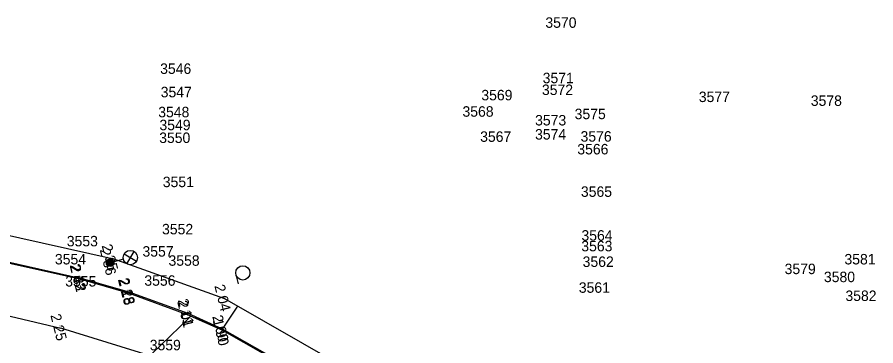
# Model space of a CAD drawing. Extents: x -740053 to -737517, y -1033516 to -1032488.
# Drawn here: x -739094.08 to -739048.92, y -1032573.66 to -1032556.4 of the extents above; entities that cross this region are included whole.
import ezdxf

# ---------------------------------------------------------------- set-up
doc = ezdxf.new("R2010")
doc.units = 0
for name, color, linetype in [('bod-cislo', 7, 'Continuous'), ('bod-oznac', 7, 'Continuous'), ('bod-vyska', 7, 'Continuous'), ('bod-vyska100', 7, 'Continuous'), ('chodnik', 7, 'Continuous'), ('Contours', 7, 'Continuous'), ('el-zariz', 7, 'Continuous'), ('osa-komunikace', 7, 'Continuous'), ('podezdivka', 7, 'Continuous'), ('silnice', 7, 'Continuous'), ('Znacky-kultury', 7, 'Continuous')]:
    doc.layers.add(name, color=color, linetype=linetype)

# ---------------------------------------------------------------- blocks, each defined once
blk = doc.blocks.new('el_lamst')
for p, q in [((-0.53, 1.658), (0.53, 2.719)), ((-0.53, 2.719), (0.53, 1.658)), ((0, 1.439), (0, 0.4))]:
    blk.add_line(p, q)
for centre, radius in [((0, 2.189), 0.75), ((0, 0), 0.4), ((0, 0), 0.351), ((0, 0), 0.305), ((0, 0), 0.305), ((0, 0), 0.26), ((0, 0), 0.206), ((0, 0), 0.161), ((0, 0), 0.115), ((0, 0), 0.0619)]:
    blk.add_circle(centre, radius)
blk = doc.blocks.new('p_zahr')
blk.add_line((0, -0.75), (0.993, -0.75))
blk.add_circle((0, 0), 0.75)
blk = doc.blocks.new('POINT_DISPLAY')
blk.add_line((0, 0), (0, 0))

msp = doc.modelspace()

# ---------------------------------------------------------------- linework, layer by layer
at = {"layer": 'chodnik'}
for p, q in [((-739098.884, -1032568.296), (-739090.768, -1032570.099)), ((-739088.189, -1032570.842), (-739090.768, -1032570.099)), ((-739085.08, -1032571.967), (-739088.189, -1032570.842)), ((-739083.274, -1032572.791), (-739085.08, -1032571.967)), ((-739073.709, -1032578.179), (-739083.274, -1032572.791))]:
    msp.add_line(p, q, dxfattribs=at)
at = {"layer": 'Contours'}
msp.add_lwpolyline([(-739113.301, -1032585.141), (-739112.468, -1032582.989), (-739111.701, -1032582.242), (-739110.056, -1032580.212), (-739109.326, -1032576.302), (-739107.888, -1032575.694), (-739099.85, -1032575.084), (-739095.564, -1032576.081), (-739094.668, -1032576.103), (-739092.396, -1032575.717), (-739091.714, -1032575.641), (-739090.99, -1032575.637), (-739087.57, -1032574.358), (-739087.088, -1032574.182), (-739086.97, -1032574.064), (-739086.008, -1032573.134), (-739085.07, -1032572.23), (-739084.95, -1032572.102), (-739084.144, -1032572.423), (-739083.274, -1032572.791), (-739082.501, -1032571.634), (-739082.49, -1032571.595), (-739082.473, -1032571.58)], dxfattribs=at)
at = {"layer": 'osa-komunikace'}
for p in [(-739099.525, -1032570.912), (-739086.9, -1032574.24)]:
    msp.add_line(p, (-739091.787, -1032572.728), dxfattribs=at)
at = {"layer": 'podezdivka'}
for p, q in [((-739098.585, -1032566.942), (-739089.089, -1032569.068)), ((-739083.163, -1032571.186), (-739089.089, -1032569.068)), ((-739072.986, -1032576.997), (-739083.163, -1032571.186))]:
    msp.add_line(p, q, dxfattribs=at)
at = {"layer": 'silnice'}
for p, q in [((-739090.763, -1032570.16), (-739098.901, -1032568.352)), ((-739088.227, -1032570.893), (-739090.763, -1032570.16)), ((-739085.116, -1032572.028), (-739088.227, -1032570.893)), ((-739083.293, -1032572.838), (-739085.116, -1032572.028)), ((-739072.867, -1032578.741), (-739083.293, -1032572.838))]:
    msp.add_line(p, q, dxfattribs=at)

# ---------------------------------------------------------------- block references
at = {"layer": 'bod-oznac', "rotation": -75.86979040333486}
for p in [(-739089.089, -1032569.068), (-739089.188, -1032569.289), (-739090.768, -1032570.099), (-739090.763, -1032570.16), (-739088.227, -1032570.893), (-739088.189, -1032570.842), (-739083.163, -1032571.186), (-739085.116, -1032572.028), (-739085.08, -1032571.967), (-739091.787, -1032572.728), (-739083.293, -1032572.838), (-739083.274, -1032572.791)]:
    msp.add_blockref('POINT_DISPLAY', p, dxfattribs=at)
at = {"layer": 'el-zariz', "xscale": 0.49999999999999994, "yscale": 0.4999999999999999, "rotation": -75.86979040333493}
msp.add_blockref('el_lamst', (-739089.188, -1032569.289), dxfattribs=at)
at = {"layer": 'Znacky-kultury', "xscale": 0.49999999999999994, "yscale": 0.5, "rotation": -75.86979040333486}
msp.add_blockref('p_zahr', (-739082.208, -1032569.826), dxfattribs=at)

# ---------------------------------------------------------------- texts
at = {"layer": 'bod-cislo'}
for s, p in [('3570', (-739066.298, -1032556.953)), ('3546', (-739086.558, -1032559.373)), ('3571', (-739066.439, -1032559.863)), ('3547', (-739086.528, -1032560.603)), ('3572', (-739066.478, -1032560.483)), ('3569', (-739069.665, -1032560.763)), ('3577', (-739058.228, -1032560.853)), ('3578', (-739052.338, -1032561.053)), ('3548', (-739086.658, -1032561.653)), ('3568', (-739070.658, -1032561.623)), ('3575', (-739064.758, -1032561.753)), ('3549', (-739086.595, -1032562.333)), ('3573', (-739066.838, -1032562.083)), ('3574', (-739066.841, -1032562.823)), ('3576', (-739064.448, -1032562.933)), ('3550', (-739086.608, -1032563.003)), ('3567', (-739069.728, -1032562.943)), ('3566', (-739064.618, -1032563.603)), ('3551', (-739086.419, -1032565.323)), ('3565', (-739064.428, -1032565.833)), ('3552', (-739086.458, -1032567.803)), ('3564', (-739064.401, -1032568.133)), ('3553', (-739091.468, -1032568.433)), ('3563', (-739064.408, -1032568.693)), ('3557', (-739087.488, -1032568.973)), ('3554', (-739092.091, -1032569.383)), ('3558', (-739086.118, -1032569.453)), ('3562', (-739064.338, -1032569.513)), ('3581', (-739050.569, -1032569.383)), ('3579', (-739053.715, -1032569.893)), ('3555', (-739091.548, -1032570.543)), ('3556', (-739087.388, -1032570.503)), ('3580', (-739051.648, -1032570.313)), ('3561', (-739064.539, -1032570.873)), ('3582', (-739050.518, -1032571.303)), ('3559', (-739087.105, -1032573.893))]:
    msp.add_text(s, height=0.55, dxfattribs=at).set_placement(p)
at = {"layer": 'bod-vyska'}
for s, p in [('2 36', (-739089.736, -1032568.614)), ('2 35', (-739089.637, -1032568.393)), ('2 43', (-739091.316, -1032569.424)), ('2 32', (-739091.311, -1032569.484)), ('2 18', (-739088.785, -1032570.179)), ('2 28', (-739088.737, -1032570.167)), ('2 04', (-739083.711, -1032570.51)), ('2 01', (-739085.664, -1032571.352)), ('2 11', (-739085.638, -1032571.254)), ('2 25', (-739092.335, -1032572.052)), ('2 00', (-739083.822, -1032572.116)), ('1 90', (-739083.803, -1032572.314))]:
    msp.add_text(s, height=0.55, rotation=284.1302, dxfattribs=at).set_placement(p)
at = {"layer": 'bod-vyska100'}
for s, p in [('292 36', (-739089.261, -1032569.135)), ('292 35', (-739089.162, -1032568.915)), ('292 43', (-739090.841, -1032569.946)), ('292 32', (-739090.836, -1032570.006)), ('292 18', (-739088.301, -1032570.736)), ('292 28', (-739088.262, -1032570.688)), ('292 04', (-739083.236, -1032571.032)), ('292 11', (-739085.154, -1032571.81)), ('292 01', (-739085.189, -1032571.874)), ('292 25', (-739091.86, -1032572.574)), ('291 90', (-739083.365, -1032572.691)), ('292 00', (-739083.347, -1032572.638))]:
    msp.add_text(s, height=0.05, rotation=284.1302, dxfattribs=at).set_placement(p)

doc.saveas('drawing.dxf')
